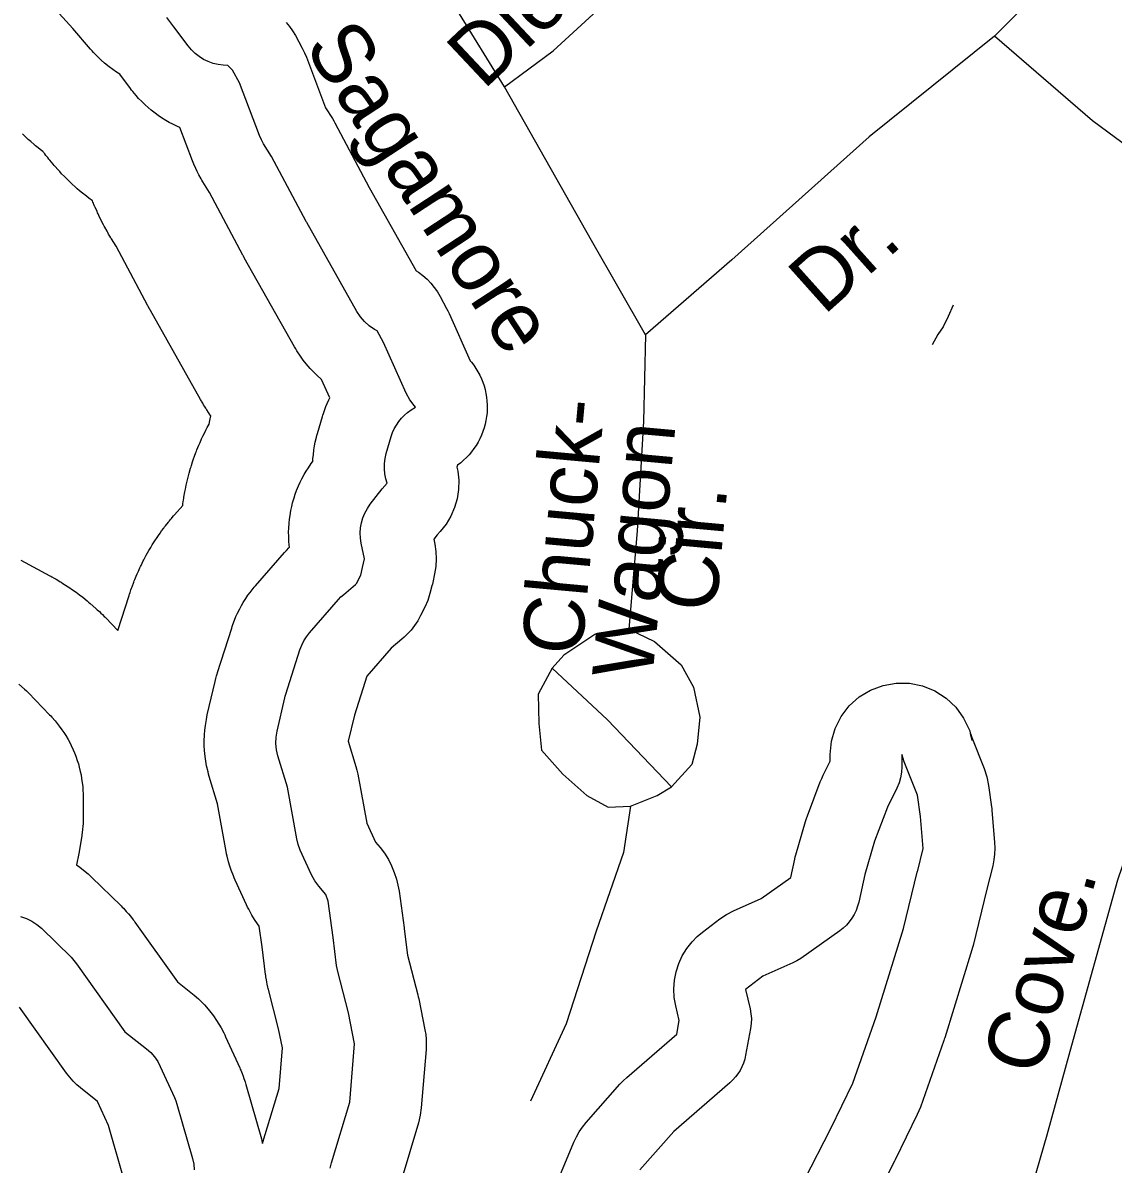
# Model space of a CAD drawing. Extents: x 2126262 to 2293712, y 749403 to 919119.
# Drawn here: x 2238925 to 2240636, y 804862 to 806654 of the extents above; entities that cross this region are included whole.
import ezdxf

# ---------------------------------------------------------------- set-up
doc = ezdxf.new("R2010")
doc.units = 0
for name, color, linetype in [('Exist Hydrographic Lake Shore', 7, 'Continuous'), ('Exist Hydrographic Misc Water Feature', 7, 'Continuous'), ('Exist Road Non-System Type 51', 7, 'Continuous'), ('Exist Road Non-System Type 51 Label', 7, 'Continuous')]:
    doc.layers.add(name, color=color, linetype=linetype)

msp = doc.modelspace()

# ---------------------------------------------------------------- linework, layer by layer
at = {"layer": 'Exist Hydrographic Lake Shore'}
for points in [[(2238918.8, 805615.5), (2238927.5, 805607.8), (2238930.7, 805604.9), (2238933.8, 805601.8), (2238967, 805567.4), (2238968.9, 805565.5), (2238970.7, 805563.5), (2238975.5, 805558), (2238978.9, 805553.9), (2238982.2, 805549.6), (2238986.4, 805543.7), (2238989.5, 805539.3), (2238992.3, 805534.7), (2238996, 805528.5), (2238998.6, 805523.7), (2239001, 805518.9), (2239004, 805512.3), (2239006.1, 805507.4), (2239008, 805502.3), (2239010.4, 805495.5), (2239012.1, 805490.4), (2239013.5, 805485.1), (2239015.2, 805478.1), (2239016.4, 805472.9), (2239017.3, 805467.5), (2239018.3, 805460.4), (2239018.9, 805455), (2239019.3, 805449.6), (2239019.7, 805442.4), (2239019.8, 805439.7), (2239019.8, 805437), (2239019.8, 805407.1), (2239019.8, 805404.9), (2239019.7, 805402.6), (2239019.5, 805396.7), (2239019.2, 805392.2), (2239018.8, 805387.8), (2239018.1, 805381.9), (2239017.8, 805379.7), (2239017.5, 805377.5), (2239013, 805349.7), (2239012.5, 805347), (2239012, 805344.2), (2239010.5, 805336.9), (2239009.3, 805331.9), (2239014.7, 805328.1), (2239020.2, 805323.6), (2239027.4, 805317.5), (2239030.1, 805315.1), (2239032.6, 805312.7), (2239079.2, 805267.2), (2239081, 805265.4), (2239082.8, 805263.6), (2239087.4, 805258.7), (2239090.7, 805254.9), (2239093.9, 805251), (2239098, 805245.7), (2239099.6, 805243.7), (2239101, 805241.7), (2239167.6, 805148.2), (2239188.7, 805131.5), (2239191.3, 805129.4), (2239193.9, 805127.2), (2239200.5, 805121.3), (2239205.4, 805116.7), (2239210, 805111.8), (2239215.9, 805105.1), (2239220.1, 805100), (2239224.1, 805094.6), (2239229.2, 805087.2), (2239232.8, 805081.6), (2239236.1, 805075.8), (2239240.3, 805067.9), (2239241.8, 805064.9), (2239243.2, 805061.9), (2239265.4, 805013.1), (2239266.3, 805011.2), (2239267.1, 805009.3), (2239269.2, 805004.1), (2239270.7, 805000.2), (2239272.1, 804996.3), (2239273.8, 804991), (2239274.4, 804989), (2239275, 804987), (2239299.4, 804901.6), (2239300.3, 804898.3), (2239301.1, 804895.1), (2239301.3, 804894.2), (2239301.9, 804896.3), (2239327.2, 804980.5), (2239332.4, 805044.3), (2239326.3, 805074.5), (2239310.4, 805136), (2239310, 805137.8), (2239309.6, 805139.6), (2239308.5, 805144.3), (2239307.8, 805147.8), (2239307.2, 805151.3), (2239306.4, 805156.1), (2239306.2, 805157.9), (2239305.9, 805159.7), (2239300.5, 805202.9), (2239296, 805235.6), (2239293.2, 805239.3), (2239288.7, 805245.9), (2239284.6, 805252.8), (2239279.5, 805262.1), (2239277.7, 805265.6), (2239276, 805269.2), (2239258.2, 805308), (2239256.8, 805311.2), (2239255.5, 805314.5), (2239252.1, 805323.2), (2239249.8, 805329.8), (2239248, 805336.6), (2239245.7, 805345.6), (2239244.9, 805349), (2239244.3, 805352.5), (2239230.6, 805427.4), (2239217.6, 805470.5), (2239216.6, 805474), (2239215.7, 805477.6), (2239213.5, 805487.1), (2239212.1, 805494.4), (2239211.1, 805501.7), (2239210.2, 805511.4), (2239209.7, 805518.8), (2239209.7, 805526.1), (2239210, 805535.9), (2239210.5, 805543.2), (2239211.5, 805550.5), (2239213.1, 805560.2), (2239213.8, 805563.8), (2239214.5, 805567.4), (2239226.7, 805619.6), (2239227, 805620.6), (2239227.3, 805621.7), (2239228, 805624.5), (2239228.5, 805626.6), (2239229.1, 805628.7), (2239230, 805631.5), (2239230.3, 805632.5), (2239230.6, 805633.6), (2239252.8, 805703.5), (2239253.7, 805706.2), (2239254.7, 805708.9), (2239257.4, 805716.1), (2239259.5, 805721.5), (2239262, 805726.7), (2239265.4, 805733.6), (2239268.1, 805738.7), (2239271, 805743.6), (2239275.1, 805750.1), (2239278.3, 805754.9), (2239281.8, 805759.5), (2239286.5, 805765.6), (2239288.3, 805767.8), (2239290.2, 805770), (2239335.7, 805822.2), (2239337.1, 805823.8), (2239338.6, 805825.4), (2239342.6, 805829.6), (2239343.5, 805830.5), (2239343.1, 805833.8), (2239342.7, 805839.8), (2239342.3, 805847.9), (2239342.2, 805854), (2239342.4, 805860.1), (2239343, 805868.1), (2239343.5, 805874.2), (2239344.4, 805880.2), (2239345.8, 805888.1), (2239347, 805894.1), (2239348.5, 805900), (2239350.7, 805907.7), (2239352.6, 805913.5), (2239354.7, 805919.2), (2239357.8, 805926.7), (2239360.2, 805932.3), (2239363, 805937.7), (2239366.8, 805944.8), (2239369.9, 805950), (2239373.2, 805955.1), (2239377.8, 805961.8), (2239379.5, 805964.3), (2239380.2, 805965.2), (2239380.4, 805969.7), (2239381, 805975.6), (2239382, 805983.5), (2239382.9, 805989.4), (2239384.1, 805995.3), (2239385.9, 806003.1), (2239386.6, 806006), (2239387.4, 806008.8), (2239395.2, 806035.5), (2239395.9, 806037.9), (2239396.7, 806040.2), (2239398.9, 806046.6), (2239400.6, 806051.3), (2239402.5, 806055.9), (2239405.2, 806062), (2239406.7, 806065.1), (2239393.9, 806093.8), (2239386.5, 806100.4), (2239381.1, 806105.5), (2239376.1, 806111), (2239369.6, 806118.5), (2239364.9, 806124.3), (2239360.7, 806130.4), (2239355.2, 806138.7), (2239353.3, 806141.8), (2239351.4, 806145), (2239272.6, 806284.8), (2239272.4, 806285.1), (2239272.3, 806285.4), (2239271.8, 806286.2), (2239271.5, 806286.8), (2239271.2, 806287.4), (2239270.7, 806288.2), (2239270.6, 806288.5), (2239270.4, 806288.8), (2239218, 806387.4), (2239207.6, 806404), (2239206.2, 806406.4), (2239204.8, 806408.7), (2239201.2, 806415.1), (2239198.6, 806420), (2239196.3, 806425), (2239193.4, 806431.7), (2239192.3, 806434.3), (2239191.3, 806436.8), (2239171.3, 806489.5), (2239167.6, 806491.1), (2239160.3, 806494.6), (2239154.8, 806497.4), (2239149.5, 806500.5), (2239142.6, 806504.7), (2239137.5, 806508.1), (2239132.6, 806511.7), (2239126.2, 806516.7), (2239121.5, 806520.6), (2239117, 806524.7), (2239111.1, 806530.4), (2239106.8, 806534.8), (2239102.8, 806539.4), (2239097.6, 806545.6), (2239095.7, 806548), (2239093.9, 806550.4), (2239077.1, 806573.1), (2239072.1, 806576.2), (2239066.1, 806580.1), (2239060.5, 806584.4), (2239053.1, 806590.4), (2239047.7, 806595), (2239042.6, 806600), (2239036.1, 806606.9), (2239033.7, 806609.5), (2239031.3, 806612.2), (2239003.7, 806644.9), (2238971.7, 806680)], [(2239407.6, 804855.6), (2239409.6, 804863.9), (2239438.4, 804959.5), (2239445.8, 805050.9), (2239436, 805099.6), (2239419.4, 805164.2), (2239418.3, 805168.9), (2239417.6, 805173.6), (2239412.1, 805217.5), (2239404.1, 805275), (2239400.8, 805285.3), (2239389.7, 805298.1), (2239383.4, 805306.7), (2239378.3, 805316), (2239360.5, 805354.8), (2239357.2, 805363.5), (2239354.9, 805372.6), (2239340.2, 805453.8), (2239325.3, 805503), (2239323.1, 805512.6), (2239322.1, 805522.3), (2239322.5, 805532.1), (2239324.1, 805541.8), (2239336.3, 805593.9), (2239337, 805596.8), (2239337.8, 805599.5), (2239360, 805669.5), (2239362.7, 805676.6), (2239366.1, 805683.5), (2239370.2, 805690), (2239375, 805696.1), (2239420.5, 805748.2), (2239424.4, 805752.4), (2239428.7, 805756.3), (2239447.3, 805772), (2239448.6, 805773.3), (2239455.3, 805786.5), (2239458.4, 805798.4), (2239461.4, 805812.3), (2239456.3, 805836.7), (2239455.1, 805844.7), (2239454.7, 805852.8), (2239455.2, 805860.9), (2239456.6, 805868.9), (2239458.9, 805876.6), (2239461.9, 805884.1), (2239465.8, 805891.2), (2239470.4, 805897.9), (2239489.2, 805922.3), (2239496.9, 805930.8), (2239494.7, 805937.9), (2239493.2, 805945.8), (2239492.5, 805953.7), (2239492.6, 805961.7), (2239493.6, 805969.6), (2239495.4, 805977.3), (2239503.2, 806004), (2239505.4, 806010.3), (2239508.1, 806016.4), (2239511.3, 806022.2), (2239515, 806027.8), (2239519.3, 806032.9), (2239523.9, 806037.7), (2239529, 806042.1), (2239534.5, 806045.9), (2239541.4, 806050.4), (2239539.4, 806052.7), (2239532.2, 806062), (2239526.7, 806072.3), (2239491.2, 806151.7), (2239481.2, 806170.1), (2239476.9, 806172.3), (2239468.7, 806177.9), (2239461.3, 806184.5), (2239454.8, 806192), (2239449.4, 806200.3), (2239370.6, 806340.1), (2239370.2, 806340.9), (2239369.7, 806341.7), (2239315.5, 806443.7), (2239303, 806463.6), (2239299.4, 806470), (2239296.5, 806476.8), (2239265, 806559.5), (2239254.1, 806579.4), (2239246.6, 806586.8), (2239239.7, 806587.2), (2239231.6, 806588.2), (2239223.7, 806590), (2239216, 806592.7), (2239208.7, 806596.2), (2239201.7, 806600.5), (2239195.3, 806605.5), (2239189.5, 806611.1), (2239184.3, 806617.4), (2239162.1, 806647.3), (2239151.2, 806662)], [(2239338.2, 806654.2), (2239343.6, 806647.7), (2239348.4, 806640.8), (2239352.8, 806633.5), (2239363.7, 806613.6), (2239367.2, 806606.7), (2239370.2, 806599.5), (2239400.3, 806520.1), (2239410.9, 806503.3), (2239412.9, 806499.9), (2239414.8, 806496.5), (2239468.8, 806394.9), (2239542.3, 806264.5), (2239546.2, 806262), (2239553, 806256.8), (2239559.4, 806251), (2239565.4, 806244.8), (2239570.8, 806238.2), (2239575.7, 806231.2), (2239580.1, 806223.8), (2239590.1, 806205.4), (2239592.1, 806201.5), (2239594, 806197.5), (2239627.1, 806123.2), (2239629.1, 806120.9), (2239632.7, 806116.1), (2239636.1, 806111.1), (2239639.3, 806105.9), (2239642.1, 806100.5), (2239644.7, 806095), (2239646.9, 806089.4), (2239648.9, 806083.6), (2239650.5, 806077.8), (2239651.8, 806071.8), (2239652.8, 806065.8), (2239653.5, 806059.8), (2239653.9, 806053.7), (2239653.9, 806047.7), (2239653.6, 806041.6), (2239652.9, 806035.6), (2239651.9, 806029.6), (2239650.7, 806023.6), (2239649.1, 806017.8), (2239647.1, 806012), (2239644.9, 806006.4), (2239642.4, 806000.8), (2239639.6, 805995.5), (2239636.4, 805990.2), (2239633.1, 805985.2), (2239629.4, 805980.4), (2239625.5, 805975.7), (2239621.3, 805971.3), (2239616.9, 805967.1), (2239612.3, 805963.1), (2239607.5, 805959.4), (2239607.4, 805959.3), (2239606.4, 805955.9), (2239607.8, 805950), (2239609.3, 805935.5), (2239609, 805921), (2239606.8, 805906.6), (2239602.7, 805892.6), (2239596.9, 805879.2), (2239589.4, 805866.7), (2239580.3, 805855.3), (2239575.6, 805850.1), (2239569.9, 805842.8), (2239571.5, 805835.3), (2239573.3, 805823.7), (2239573.9, 805812), (2239573.2, 805800.3), (2239571.4, 805788.7), (2239568.4, 805774.9), (2239567.8, 805772.3), (2239567.2, 805769.8), (2239564.1, 805757.9), (2239560.5, 805746.9), (2239555.9, 805736.2), (2239549.3, 805723), (2239544.9, 805715.1), (2239539.9, 805707.5), (2239534.3, 805700.4), (2239528.2, 805693.7), (2239526.9, 805692.4), (2239523.4, 805689.1), (2239519.8, 805685.9), (2239503.4, 805672.1), (2239464.9, 805628), (2239445.5, 805566.9), (2239435.9, 805525.9), (2239447.9, 805486.4), (2239449.5, 805480.2), (2239450.9, 805474), (2239464.8, 805397.3), (2239478.4, 805367.6), (2239486, 805358.8), (2239492.9, 805349.9), (2239498.9, 805340.4), (2239503.9, 805330.3), (2239507.9, 805319.7), (2239511.3, 805309.4), (2239513.8, 805299.9), (2239515.6, 805290.3), (2239523.5, 805232.9), (2239523.6, 805232.2), (2239523.7, 805231.5), (2239528.9, 805190), (2239545, 805127.8), (2239545.7, 805124.7), (2239546.4, 805121.7), (2239556.1, 805073), (2239557.4, 805065.3), (2239558.1, 805057.5), (2239558.3, 805049.7), (2239557.9, 805041.9), (2239550.5, 804950.4), (2239548.9, 804938.6), (2239546.1, 804927), (2239518.6, 804835.6)], [(2238922.1, 805810), (2238967.6, 805785.6), (2238969, 805784.8), (2238970.4, 805784), (2238974.2, 805781.9), (2238977.1, 805780.2), (2238979.9, 805778.6), (2238983.6, 805776.3), (2238985, 805775.4), (2238986.3, 805774.5), (2238996.1, 805768.3), (2238998.8, 805766.5), (2239001.5, 805764.7), (2239008.7, 805759.7), (2239014, 805755.9), (2239019.1, 805751.8), (2239025.8, 805746.3), (2239028.3, 805744.2), (2239030.8, 805742.1), (2239039.5, 805734.4), (2239040.7, 805733.3), (2239041.9, 805732.2), (2239045.1, 805729.3), (2239047.5, 805727), (2239049.8, 805724.7), (2239052.9, 805721.7), (2239054.1, 805720.5), (2239055.2, 805719.4), (2239074.3, 805699.7), (2239091.7, 805754.6), (2239092, 805755.7), (2239092.4, 805756.7), (2239093.3, 805759.4), (2239094, 805761.5), (2239094.7, 805763.5), (2239095.7, 805766.2), (2239096.1, 805767.2), (2239096.4, 805768.3), (2239099.1, 805775.5), (2239099.9, 805777.5), (2239100.7, 805779.5), (2239102.9, 805784.8), (2239104.5, 805788.8), (2239106.3, 805792.8), (2239108.7, 805798), (2239109.7, 805800), (2239110.6, 805801.9), (2239114, 805808.8), (2239115, 805810.7), (2239116, 805812.6), (2239118.7, 805817.7), (2239120.8, 805821.5), (2239123, 805825.3), (2239125.9, 805830.2), (2239127, 805832.1), (2239128.2, 805833.9), (2239132.3, 805840.4), (2239133.4, 805842.2), (2239134.6, 805844), (2239137.8, 805848.8), (2239140.3, 805852.4), (2239142.8, 805855.9), (2239146.3, 805860.5), (2239147.6, 805862.3), (2239148.9, 805864), (2239153.7, 805870), (2239154.3, 805870.9), (2239155, 805871.7), (2239156.8, 805873.9), (2239158.2, 805875.6), (2239159.6, 805877.3), (2239161.4, 805879.5), (2239162.1, 805880.3), (2239162.9, 805881.1), (2239176, 805896.1), (2239176.3, 805898.6), (2239177.2, 805904.6), (2239177.5, 805906.9), (2239177.9, 805909.2), (2239179.3, 805917.1), (2239179.7, 805919.4), (2239180.1, 805921.6), (2239181.3, 805927.6), (2239182.3, 805932), (2239183.4, 805936.4), (2239184.9, 805942.3), (2239185.5, 805944.5), (2239186.1, 805946.7), (2239188.3, 805954.5), (2239189, 805956.7), (2239189.6, 805958.8), (2239191.5, 805964.6), (2239192.9, 805969), (2239194.5, 805973.2), (2239196.6, 805978.9), (2239197.4, 805981), (2239198.3, 805983.2), (2239201.3, 805990.7), (2239202.2, 805992.8), (2239203.1, 805994.8), (2239205.6, 806000.4), (2239207.5, 806004.6), (2239209.5, 806008.6), (2239212.2, 806014.1), (2239213.3, 806016.1), (2239214.3, 806018.1), (2239217.4, 806023.7), (2239218.6, 806029.5), (2239219.1, 806031.7), (2239219.6, 806033.9), (2239220.2, 806036.5), (2239219.2, 806037.9), (2239213.8, 806046.2), (2239213, 806047.3), (2239212.3, 806048.5), (2239210.3, 806051.7), (2239208.8, 806054), (2239207.4, 806056.4), (2239205.5, 806059.6), (2239204.8, 806060.8), (2239204.1, 806062.1), (2239125.4, 806201.9), (2239125.3, 806202), (2239125.2, 806202.1), (2239125.1, 806202.4), (2239124.9, 806202.6), (2239124.8, 806202.8), (2239124.6, 806203.1), (2239124.6, 806203.3), (2239124.5, 806203.4), (2239124.1, 806204.2), (2239124, 806204.4), (2239123.8, 806204.6), (2239123.5, 806205.2), (2239123.3, 806205.7), (2239123, 806206.1), (2239122.7, 806206.7), (2239122.6, 806206.9), (2239122.4, 806207.2), (2239122, 806208), (2239121.9, 806208.1), (2239121.9, 806208.2), (2239121.7, 806208.5), (2239121.6, 806208.7), (2239121.5, 806208.9), (2239121.3, 806209.2), (2239121.3, 806209.4), (2239121.2, 806209.5), (2239071.6, 806302.8), (2239064.3, 806314.4), (2239063.7, 806315.3), (2239063.2, 806316.2), (2239061.8, 806318.5), (2239060.7, 806320.3), (2239059.7, 806322.1), (2239058.3, 806324.5), (2239057.8, 806325.4), (2239057.3, 806326.3), (2239053.7, 806332.7), (2239052.7, 806334.5), (2239051.7, 806336.3), (2239049.2, 806341.2), (2239047.3, 806344.9), (2239045.5, 806348.6), (2239043.1, 806353.6), (2239042.3, 806355.5), (2239041.4, 806357.3), (2239038.5, 806364.1), (2239038.1, 806365), (2239037.7, 806366), (2239036.6, 806368.5), (2239035.8, 806370.4), (2239035.1, 806372.3), (2239034.3, 806374.2), (2239032.4, 806375.6), (2239030.6, 806377), (2239028.7, 806378.4), (2239022.3, 806383.4), (2239020.5, 806384.8), (2239018.7, 806386.3), (2239014, 806390.1), (2239010.5, 806393.1), (2239007.1, 806396.2), (2239002.6, 806400.3), (2239000.9, 806401.9), (2238999.3, 806403.4), (2238993.4, 806409.1), (2238991.8, 806410.7), (2238990.2, 806412.4), (2238985.9, 806416.7), (2238982.8, 806420.1), (2238979.7, 806423.5), (2238975.7, 806428.1), (2238974.2, 806429.8), (2238972.7, 806431.6), (2238967.5, 806437.8), (2238966.8, 806438.7), (2238966, 806439.6), (2238964.1, 806442), (2238962.7, 806443.8), (2238961.3, 806445.6), (2238959.4, 806448), (2238958.7, 806448.9), (2238958.1, 806449.9), (2238957.8, 806450.2), (2238956.3, 806451.4), (2238954.2, 806453), (2238946.8, 806459), (2238944.7, 806460.7), (2238942.7, 806462.4), (2238937.3, 806467.1), (2238933.3, 806470.6), (2238929.5, 806474.3), (2238924.4, 806479.3)], [(2239767.7, 804843.8), (2239790, 804896.7), (2239793.9, 804904.9), (2239798.4, 804912.7), (2239803.5, 804920.2), (2239809.2, 804927.2), (2239862.1, 804987.5), (2239867.3, 804993), (2239872.9, 804998.2), (2239951.3, 805066.2), (2239955.2, 805087.7), (2239949.9, 805110.5), (2239947.6, 805123.8), (2239946.9, 805137.3), (2239947.8, 805150.7), (2239950.4, 805163.9), (2239954.5, 805176.8), (2239960.1, 805189.1), (2239967.1, 805200.6), (2239975.5, 805211.1), (2239975.6, 805211.2), (2239983.4, 805219.2), (2239992, 805226.3), (2240019.3, 805246.8), (2240029.6, 805253.7), (2240040.7, 805259.4), (2240084.1, 805278.9), (2240130.3, 805311.7), (2240136.7, 805340.6), (2240137.5, 805344.2), (2240138.5, 805347.7), (2240153.6, 805400.1), (2240155, 805404.5), (2240156.5, 805408.8), (2240176.8, 805462.3), (2240179, 805467.6), (2240181.4, 805472.7), (2240192.4, 805494.7), (2240192.4, 805505.1), (2240194.3, 805525.9), (2240200.1, 805546), (2240209.5, 805564.7), (2240222.2, 805581.4), (2240237.7, 805595.4), (2240255.6, 805606.2), (2240275.2, 805613.6), (2240295.8, 805617.2), (2240316.8, 805616.9), (2240337.3, 805612.8), (2240356.7, 805604.9), (2240374.3, 805593.6), (2240389.5, 805579.2), (2240401.7, 805562.3), (2240410.7, 805543.3), (2240414.9, 805527), (2240412.3, 805538), (2240414.4, 805531.5), (2240433.8, 805482.8), (2240438.1, 805469.8), (2240440.8, 805456.3), (2240445.4, 805422.9), (2240445.8, 805420.1), (2240446, 805417.3), (2240450.3, 805367.3), (2240450.8, 805358), (2240450.4, 805348.7), (2240449.3, 805339.5), (2240447.4, 805330.4), (2240438.3, 805293.8), (2240416.6, 805205.1), (2240415.8, 805201.8), (2240414.8, 805198.6), (2240372.1, 805060.2), (2240371.4, 805058), (2240370.7, 805055.8), (2240333.8, 804951.4), (2240331.5, 804945.5), (2240328.9, 804939.8), (2240294.5, 804868.8), (2240293.9, 804867.7), (2240293.4, 804866.7), (2240252.1, 804785.9)], [(2240151.9, 804837.1), (2240193.3, 804917.9), (2240227.7, 804988.9), (2240264.6, 805093.3), (2240307.3, 805231.8), (2240329, 805320.5), (2240329, 805320.8), (2240329.1, 805321), (2240338.3, 805357.6), (2240334, 805407.6), (2240329.4, 805441), (2240308.4, 805493.5), (2240305, 805504), (2240304.9, 805505.1), (2240304.9, 805485.9), (2240304.4, 805477.2), (2240302.9, 805468.6), (2240300.4, 805460.3), (2240297, 805452.3), (2240282, 805422.4), (2240261.7, 805368.9), (2240246.6, 805316.5), (2240237.1, 805273.4), (2240235.3, 805266.7), (2240232.9, 805260.2), (2240229.9, 805254), (2240226.4, 805248), (2240222.3, 805242.5), (2240217.7, 805237.3), (2240212.7, 805232.5), (2240207.2, 805228.3), (2240146.2, 805185), (2240140, 805181.1), (2240133.5, 805177.8), (2240086.8, 805156.8), (2240059.5, 805136.3), (2240059.4, 805136.2), (2240066.5, 805105.8), (2240067.9, 805098.1), (2240068.5, 805090.4), (2240068.3, 805082.7), (2240067.3, 805075), (2240059.5, 805032.9), (2240058.1, 805026.7), (2240056.2, 805020.7), (2240053.8, 805014.9), (2240050.9, 805009.2), (2240047.5, 805003.9), (2240043.7, 804998.8), (2240039.5, 804994.1), (2240034.9, 804989.8), (2239946.6, 804913.2), (2239893.7, 804853)], [(2238921.5, 805250.8), (2238930.5, 805247.7), (2238939, 805243.6), (2238946.9, 805238.3), (2238954.1, 805232.2), (2239000.7, 805186.7), (2239005.2, 805181.8), (2239009.4, 805176.5), (2239085.3, 805069.8), (2239119, 805043.2), (2239125.7, 805037.3), (2239131.6, 805030.6), (2239136.7, 805023.2), (2239140.8, 805015.4), (2239163, 804966.5), (2239165.1, 804961.4), (2239166.8, 804956.1), (2239191.3, 804870.7), (2239193.2, 804861.9), (2239194.1, 804853.1)], [(2239081.9, 804844.1), (2239059.4, 804922.5), (2239042.2, 804960.5), (2239015.6, 804981.5), (2239009.5, 804986.7), (2239003.8, 804992.3), (2238998.5, 804998.3), (2238993.6, 805004.6), (2238919.7, 805108.5)]]:
    msp.add_lwpolyline(points, dxfattribs=at)
at = {"layer": 'Exist Hydrographic Misc Water Feature'}
msp.add_lwpolyline([(2240385.1, 806210.6), (2240377.3, 806192.6), (2240369.5, 806176.6), (2240361.5, 806164.5), (2240352.5, 806147.9)], dxfattribs=at)
at = {"layer": 'Exist Road Non-System Type 51'}
for points in [[(2239681.3, 806553), (2239606, 806674.5), (2239551.6, 806775.1), (2239518.1, 806857.5), (2239511.8, 806955.9), (2239548.1, 807095.6), (2239629.7, 807305.8), (2239678.5, 807423.1)], [(2240450.3, 806632.6), (2240500.5, 806682.9), (2240536.8, 806737.4), (2240559.1, 806797.4), (2240557.7, 806945.5), (2240554.2, 807222.7), (2240552.8, 807361)], [(2239681.3, 806553), (2239757.4, 806609.6), (2239932.5, 806770.9), (2240035.8, 806878.4)], [(2240450.3, 806632.6), (2240253.5, 806474.8), (2240037.9, 806281.3), (2239902.5, 806164)], [(2240732.2, 806404.9), (2240603.8, 806499.9), (2240450.3, 806632.6)], [(2239902.5, 806164), (2239817.4, 806312.1), (2239681.3, 806553)], [(2239902.5, 806164), (2239899, 806027.8), (2239889.3, 805856), (2239876, 805701.7)], [(2239876, 805701.7), (2239823, 805693.3), (2239774.1, 805661.2), (2239756, 805640.3)], [(2239876, 805701.7), (2239916.5, 805682.2), (2239958.3, 805645.8), (2239977.9, 805610.9), (2239987.7, 805563.4), (2239983.5, 805521.5), (2239975.1, 805489.4), (2239943, 805454.5)], [(2239756, 805640.3), (2239733.7, 805599.7), (2239735.1, 805553.7), (2239739.3, 805511.8), (2239772.7, 805474), (2239810.4, 805440.5), (2239843.9, 805422.4), (2239878.8, 805423.8)], [(2239756, 805640.3), (2239842.5, 805559.2), (2239943, 805454.5)], [(2240758.9, 805620.4), (2240701.7, 805479.3), (2240643.1, 805307.5), (2240568.4, 805038.7), (2240532.1, 804907.4), (2240493.1, 804771.9), (2240458.9, 804607.8), (2240429.6, 804434.6), (2240411.4, 804285.2)], [(2239878.8, 805423.8), (2239920.7, 805440.5), (2239943, 805454.5)], [(2239878.8, 805423.8), (2239867.6, 805351.1), (2239825.1, 805227.5), (2239777.6, 805082.3), (2239721.8, 804960.8)]]:
    msp.add_lwpolyline(points, dxfattribs=at)

# ---------------------------------------------------------------- texts
at = {"layer": 'Exist Road Non-System Type 51 Label'}
for s, rotation, p in [('Diego', 43.2523, (2239648, 806547)), ('Sagamore', 303.2057, (2239365.3, 806615.9)), ('Dr.', 41.8246, (2240182.1, 806193.2)), ('Chuck-', 84.7846, (2239802.1, 805658.6)), ('Wagon', 84.7846, (2239913, 805621.6)), ('Cir.', 84.7846, (2240013, 805727.1)), ('Cove.', 74.1564, (2240521.4, 804997.8))]:
    msp.add_text(s, height=95, rotation=rotation, dxfattribs=at).set_placement(p)

doc.saveas('drawing.dxf')
